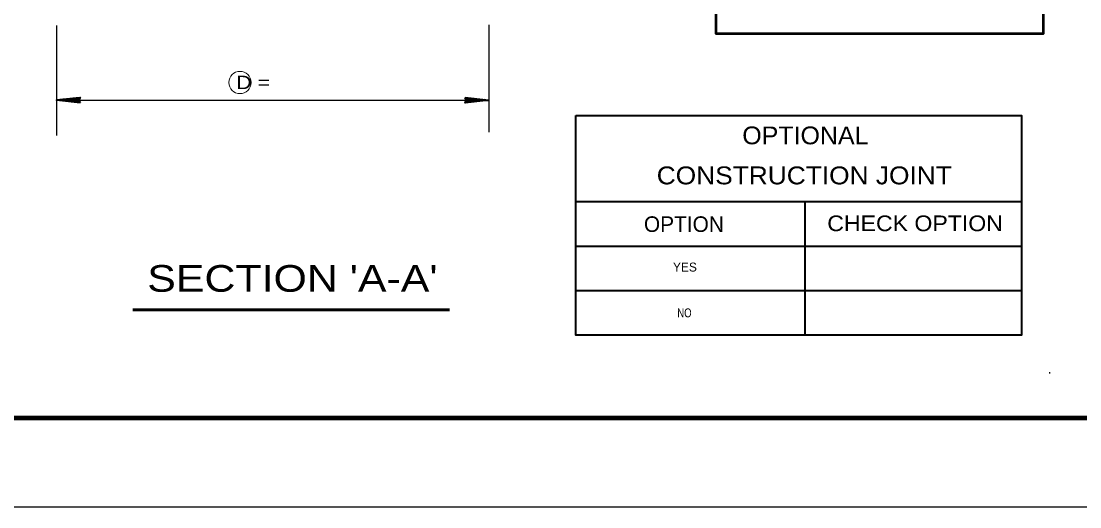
# Model space of a CAD drawing. Extents: x 1.6 to 19.9, y 2.8 to 9.5.
# Drawn here: x 17.696 to 18.624, y 7.289 to 7.715 of the extents above; entities that cross this region are included whole.
import ezdxf
from ezdxf.enums import TextEntityAlignment as Align

# ---------------------------------------------------------------- set-up
doc = ezdxf.new("R2010")
doc.units = 0
doc.header["$LTSCALE"] = 0.0047
doc.layers.add('1', color=7, linetype='Continuous', lineweight=35)
doc.layers.add('5', color=7, linetype='Continuous', lineweight=13)

msp = doc.modelspace()

# ---------------------------------------------------------------- linework, layer by layer
at = {"layer": '1', "lineweight": 25}
for p, q in [((17.727083, 7.71125), (17.727083, 7.614667)), ((18.106167, 7.711833), (18.106167, 7.6175)), ((17.729167, 7.64575), (18.103917, 7.64575)), ((18.597417, 7.406917), (18.597417, 7.405917)), ((16.26675, 7.288833), (19.894917, 7.288833))]:
    msp.add_line(p, q, dxfattribs=at)
at = {"layer": '1'}
for p, q in [((17.747917, 7.64575), (17.727167, 7.64575)), ((17.747417, 7.64425), (17.732083, 7.645917)), ((17.747417, 7.644), (17.732083, 7.64575)), ((17.747417, 7.64775), (17.733, 7.64625)), ((17.747417, 7.647583), (17.733, 7.646)), ((17.747417, 7.647333), (17.733083, 7.64575)), ((17.747417, 7.647167), (17.733083, 7.645583)), ((18.085167, 7.64575), (18.106083, 7.64575)), ((18.0855, 7.6445), (18.100083, 7.646)), ((18.085583, 7.64775), (18.101167, 7.646)), ((18.085583, 7.647667), (18.101167, 7.646)), ((18.085583, 7.647583), (18.101167, 7.645917)), ((18.085583, 7.647333), (18.101167, 7.645667)), ((18.085583, 7.64425), (18.100083, 7.64575)), ((18.085667, 7.647833), (18.101167, 7.646083)), ((17.747417, 7.643833), (17.732, 7.645583)), ((17.747417, 7.643917), (17.732, 7.645583)), ((17.747417, 7.64375), (17.732, 7.6455)), ((18.085583, 7.644), (18.100167, 7.645583)), ((18.085667, 7.64375), (18.100167, 7.645417)), ((18.182417, 7.55675), (18.573, 7.55675)), ((18.383333, 7.43925), (18.383333, 7.556417)), ((18.182417, 7.517667), (18.573, 7.517667)), ((18.182417, 7.478583), (18.573, 7.478583))]:
    msp.add_line(p, q, dxfattribs=at)
at = {"layer": '1', "lineweight": 60}
msp.add_line((17.793917, 7.461833), (18.071667, 7.461833), dxfattribs=at)
at = {"layer": '1', "lineweight": 106}
msp.add_line((16.423, 7.367), (19.823, 7.367), dxfattribs=at)
at = {"layer": '1', "lineweight": 53}
msp.add_lwpolyline([(18.305167, 7.788083), (18.591833, 7.788083), (18.591833, 7.703917), (18.305167, 7.703917)], close=True, dxfattribs=at)
at = {"layer": '1', "lineweight": 40}
msp.add_lwpolyline([(16.423, 7.367), (19.148, 7.367), (19.148, 7.742), (19.823, 7.742)], dxfattribs=at)
at = {"layer": '1'}
for points in [[(17.747917, 7.6435), (17.727167, 7.64575), (17.747917, 7.648167), (17.74675, 7.64575)], [(17.746417, 7.645583), (17.73725, 7.645417), (17.73725, 7.645667), (17.739, 7.645583), (17.746417, 7.645417), (17.7405, 7.64525), (17.746667, 7.645083), (17.742333, 7.645), (17.746833, 7.64475), (17.739833, 7.64525), (17.730583, 7.645667), (17.732417, 7.64625), (17.729917, 7.646), (17.746417, 7.646), (17.741667, 7.646333), (17.746667, 7.646333), (17.736167, 7.645583), (17.74675, 7.64675)], [(18.085167, 7.648083), (18.106083, 7.64575), (18.085167, 7.6435), (18.086333, 7.64575)], [(18.086667, 7.646), (18.095917, 7.64625), (18.095833, 7.646), (18.094167, 7.646), (18.086667, 7.64625), (18.092667, 7.646333), (18.086417, 7.6465), (18.090667, 7.646667), (18.086167, 7.646917), (18.093333, 7.646333), (18.102583, 7.646), (18.100667, 7.645417), (18.10325, 7.645667), (18.086667, 7.645583), (18.091417, 7.64525), (18.086417, 7.64525), (18.096917, 7.646), (18.086167, 7.644833)], [(18.182417, 7.632167), (18.573, 7.632167), (18.573, 7.4395), (18.182417, 7.4395)]]:
    msp.add_lwpolyline(points, close=True, dxfattribs=at)
for points in [[(17.746417, 7.645583), (17.74725, 7.644167), (17.74675, 7.6445), (17.746417, 7.64525), (17.745833, 7.645), (17.746167, 7.644417), (17.7465, 7.645917), (17.746917, 7.64675), (17.747417, 7.64775)], [(18.086667, 7.646), (18.08575, 7.6475), (18.086167, 7.647167), (18.086667, 7.646333), (18.087167, 7.646583), (18.08675, 7.64725), (18.086417, 7.64575), (18.086083, 7.644833), (18.085667, 7.643833)]]:
    msp.add_lwpolyline(points, dxfattribs=at)
at = {"layer": '1', "lineweight": 13}
msp.add_circle((17.887941, 7.661216), 0.009766, dxfattribs=at)

# ---------------------------------------------------------------- texts
at = {"layer": '1'}
for s, height, width, p in [('OPTIONAL', 0.01558, 1.05, (18.3835, 7.607)), ('CONSTRUCTION JOINT', 0.01567, 1.1, (18.382542, 7.571833)), ('NO', 0.007833, 0.8, (18.2775, 7.455167))]:
    msp.add_text(s, height=height, dxfattribs=dict(at, width=width)).set_placement(p, align=Align.CENTER)
msp.add_text('OPTION', height=0.01367, dxfattribs=at).set_placement((18.242, 7.530083))
for s, height, width, p in [('CHECK OPTION', 0.01375, 1.1, (18.402667, 7.53075)), ("SECTION 'A-A'", 0.02342, 1.2, (17.806667, 7.477583))]:
    msp.add_text(s, height=height, dxfattribs=dict(at, width=width)).set_placement(p)
msp.add_text('YES', height=0.007833, dxfattribs=at).set_placement((18.277917, 7.495333), align=Align.CENTER)
at = {"layer": '5', "width": 1.2}
msp.add_text('D =      ', height=0.01175, dxfattribs=at).set_placement((17.884583, 7.655417))

doc.saveas('drawing.dxf')
